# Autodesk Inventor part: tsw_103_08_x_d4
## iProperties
Created: 2006-03
Part Number: tsw_103_08_x_d4
Document SubType Name: Modeling
Designer: Elise Moss
Author: Elise Moss
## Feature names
1. Base1
